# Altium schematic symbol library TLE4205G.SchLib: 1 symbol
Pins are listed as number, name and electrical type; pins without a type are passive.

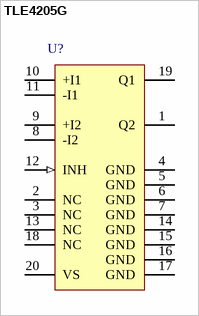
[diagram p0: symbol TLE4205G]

## TLE4205G
designator U?
1 A DC Motor Driver, -40 to 150 degC, P-DSO-20-17, Reel; Manufacturer: Infineon; PartNumber: TLE4205G; Green: FALSE; Group: Servo Driver; Inhibit: TRUE; IPeak: 2 x 1 A; Iq: 2 x 0.6 A; Iq (typ): 10 uA; Protect: Short to GND
footprint INF-P-DSO-20-17_N (SOP, 20-Leads, Body 12.7x7.5mm, Pitch 1.27mm, IPC Medium Density)
footprint INF-P-DSO-20-17_L (SOP, 20-Leads, Body 12.7x7.5mm, Pitch 1.27mm, IPC High Density)
footprint INF-P-DSO-20-17_M (SOP, 20-Leads, Body 12.7x7.5mm, Pitch 1.27mm, IPC Low Density)
pins: 1 Q2 (power) "Output 2 of channel 2; push-pull B output with DC short-circuit  protection to ground. Integrated free-wheeling diodes to ground  and the supply voltage.", 2 NC "Not connected", 3 NC "Not connected", 4 GND (power) "Ground", 5 GND (power) "Ground", 6 GND (power) "Ground", 7 GND (power) "Ground", 8 -I2 (power) "Inverting input channel 2; to be wired according to general  rules.", 9 +I2 (power) "Non-inverting input channel 2; to be wired according to  general rules.", 10 +I1 (power) "Non-inverting input channel 1; see pin 9.", 11 -I1 (power) "Inverting input channel 1; see pin 8", 12 INH (in) "Inhibit; the IC is passive when this pin is open or connected to  ground.", 13 NC "Not connected", 14 GND (power) "Ground", 15 GND (power) "Ground", 16 GND (power) "Ground", 17 GND (power) "Ground", 18 NC "Not connected", 19 Q1 (power) "Output Q1 of channel 1, see pin 1.", 20 VS (power) "Supply voltageVS; must be blocked with a ceramic capacitor  of at least 100 nF directly on the pins of the IC"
